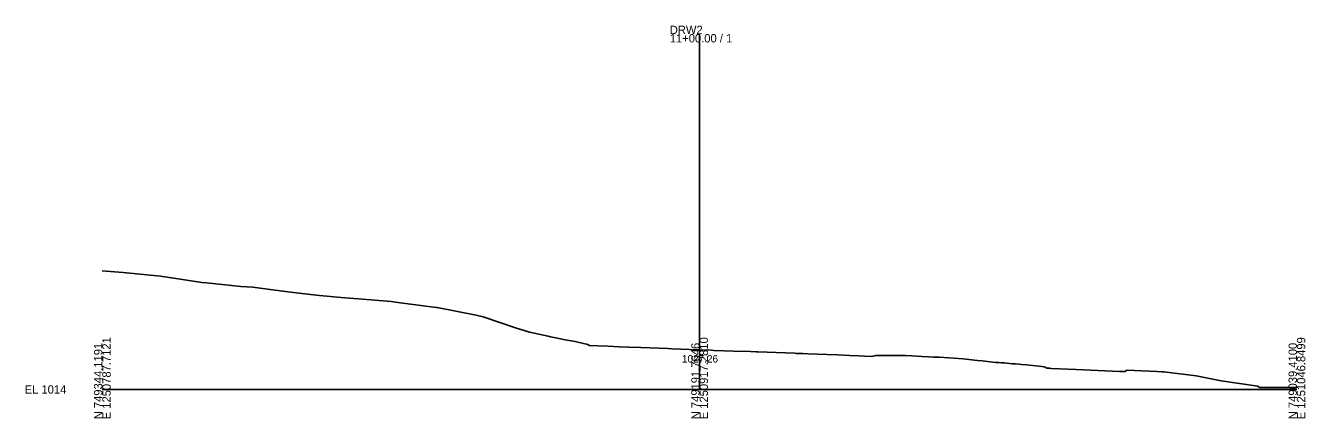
# Model space of a CAD drawing. Extents: x -26 to 403, y -366 to 1122.
# Drawn here: x -25.7 to 402.8, y 990.3 to 1121.8 of the extents above; entities that cross this region are included whole.
import ezdxf

# ---------------------------------------------------------------- set-up
doc = ezdxf.new("R2010")
doc.units = 0
for name, color, linetype in [('Default', 7, 'Continuous'), ('Exist Cross Section Cell', 7, 'Continuous'), ('Exist XS Center Line Elevation Label', 7, 'Continuous'), ('Exist XS Ground Line', 7, 'Continuous')]:
    doc.layers.add(name, color=color, linetype=linetype)

msp = doc.modelspace()

# ---------------------------------------------------------------- linework, layer by layer
at = {"layer": 'Exist Cross Section Cell'}
for p, q in [((200, 1000), (200, 1118.96)), ((0, 1000), (200, 1000)), ((200, 1000), (400, 1000))]:
    msp.add_line(p, q, dxfattribs=at)
at = {"layer": 'Exist XS Ground Line'}
msp.add_lwpolyline([(0, 1039.65), (4.05, 1039.4), (7.03, 1039.13), (19.49, 1037.89), (20.15, 1037.8), (23.95, 1037.26), (33.28, 1035.85), (34.92, 1035.67), (46.41, 1034.49), (50.36, 1034.21), (59.54, 1033.02), (65.8, 1032.23), (72.67, 1031.49), (81.24, 1030.63), (85.8, 1030.31), (96.68, 1029.41), (98.93, 1029.12), (111.74, 1027.43), (112.11, 1027.39), (125.19, 1024.86), (127.55, 1024.31), (138.32, 1020.62), (142.99, 1019.19), (149.34, 1017.8), (150.11, 1017.62), (151.87, 1017.25), (154.93, 1016.62), (158.32, 1016.01), (161.6, 1015.28), (162.26, 1015.14), (163.15, 1014.67), (165.88, 1014.58), (169.34, 1014.45), (173.11, 1014.31), (176.32, 1014.19), (180.36, 1014.05), (189.3, 1013.69), (190.83, 1013.63), (199.53, 1013.28), (200, 1013.26), (203.96, 1013.1), (204.74, 1013.07), (211.41, 1012.86), (217.09, 1012.65), (218.82, 1012.59), (219.14, 1012.57), (219.51, 1012.56), (231.87, 1012.09), (232.36, 1012.08), (232.92, 1012.06), (233.28, 1012.05), (234.52, 1012.01), (236.31, 1011.95), (242.7, 1011.73), (246.32, 1011.56), (250.15, 1011.41), (253.35, 1011.21), (255.23, 1011.13), (257.64, 1011.02), (258.08, 1011.16), (258.97, 1011.41), (261.21, 1011.41), (264.04, 1011.4), (266.57, 1011.37), (268.89, 1011.34), (271.03, 1011.29), (274.37, 1011), (276.72, 1010.92), (278.38, 1010.84), (280.16, 1010.75), (281.86, 1010.65), (283.5, 1010.56), (285.1, 1010.46), (286.68, 1010.36), (288.25, 1010.25), (293.06, 1009.69), (294.64, 1009.58), (299.12, 1009.07), (300.21, 1008.99), (301.06, 1008.93), (301.92, 1008.86), (302.79, 1008.79), (303.71, 1008.71), (304.69, 1008.62), (305.76, 1008.53), (306.96, 1008.41), (307.74, 1008.35), (309.42, 1008.2), (311.61, 1008), (314.64, 1007.7), (315.4, 1007.62), (315.91, 1007.32), (316.25, 1007.12), (317.22, 1007.07), (317.73, 1007.05), (320.46, 1006.9), (326.11, 1006.63), (340.57, 1006.06), (341.67, 1006.02), (342.48, 1005.99), (343.04, 1006.44), (350.59, 1006.11), (353.05, 1006.02), (354.72, 1005.95), (355.49, 1005.84), (366.25, 1004.55), (374.67, 1002.83), (386.93, 1001.12), (387.49, 1000.67), (400, 1000.62)], dxfattribs=at)

# ---------------------------------------------------------------- texts
at = {"layer": 'Default'}
msp.add_text('-', height=0.0001, dxfattribs=at).set_placement((0, 1000))
msp.add_text('-', height=0.0001, dxfattribs=at).set_placement((0, 1000))
at = {"layer": 'Exist Cross Section Cell'}
for s, p in [('11+00.00 / 1', (190, 1116.16)), ('DRW2', (190, 1118.96)), ('EL 1014', (-26, 998.6))]:
    msp.add_text(s, height=2.8, dxfattribs=at).set_placement(p)
for s, p in [('E 1250787.7121', (2.8, 990)), ('E 1250917.2810', (202.8, 990)), ('E 1251046.8499', (402.8, 990)), ('N 749344.1191', (0, 990)), ('N 749191.7646', (200, 990)), ('N 749039.4100', (400, 990))]:
    msp.add_text(s, height=2.8, rotation=90, dxfattribs=at).set_placement(p)
at = {"layer": 'Exist XS Center Line Elevation Label'}
msp.add_text('1027.26', height=2.5, dxfattribs=at).set_placement((194.09, 1009.01))

doc.saveas('drawing.dxf')
